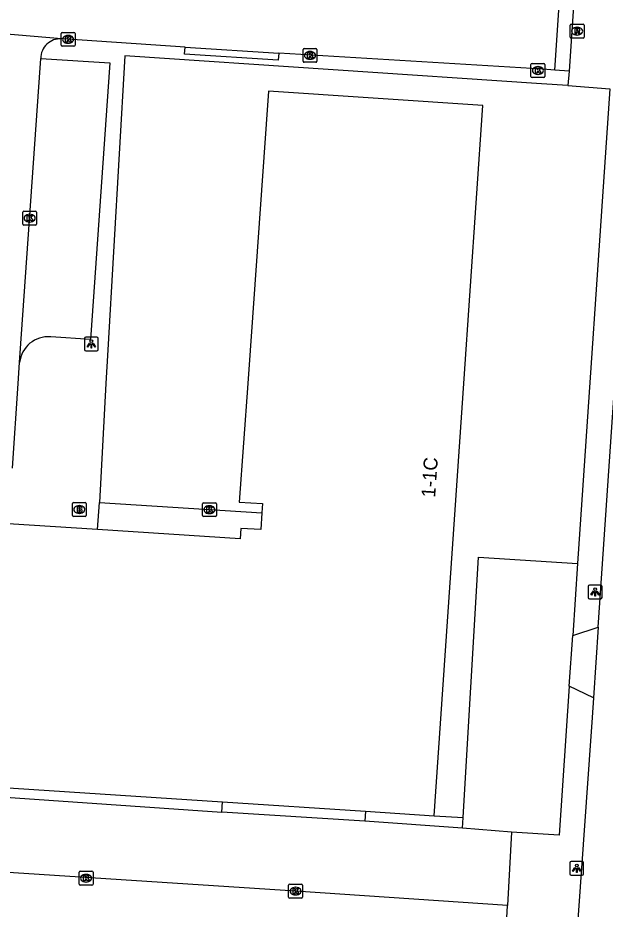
# Model space of a CAD drawing. Extents: x 161848 to 162726, y 385382 to 386521.
# Drawn here: x 161953.7 to 161996.1, y 385462 to 385526.4 of the extents above; entities that cross this region are included whole.
import ezdxf

# ---------------------------------------------------------------- set-up
doc = ezdxf.new("R2010")
doc.units = 0
for name, color, linetype in [('IMGEO_Brandkraan', 7, 'Continuous'), ('IMGEO_Fietspad_gesloten', 7, 'Continuous'), ('IMGEO_Kolk', 7, 'Continuous'), ('IMGEO_Lichtpunt', 7, 'Continuous'), ('IMGEO_Pand', 7, 'Continuous'), ('IMGEO_Pand_nummerreeks', 7, 'Continuous'), ('IMGEO_Parkeervlak_open', 7, 'Continuous'), ('IMGEO_Rijbaan_lokaal_open', 7, 'Continuous'), ('IMGEO_Rioolput', 7, 'Continuous'), ('IMGEO_Voetpad_open', 7, 'Continuous')]:
    doc.layers.add(name, color=color, linetype=linetype)

msp = doc.modelspace()

# ---------------------------------------------------------------- linework, layer by layer
at = {"layer": 'IMGEO_Brandkraan'}
for p, q in [((161957.602, 385490.47), (161957.602, 385491.322)), ((161957.677, 385491.396), (161958.529, 385491.396)), ((161958.603, 385491.322), (161958.603, 385490.47)), ((161958.09, 385491.176), (161958.115, 385491.176)), ((161958.529, 385490.396), (161957.677, 385490.396)), ((161958.113, 385490.616), (161958.088, 385490.616))]:
    msp.add_line(p, q, dxfattribs=at)
for points in [[(161957.602, 385490.47), (161957.602, 385491.322)], [(161957.677, 385491.396), (161958.529, 385491.396)], [(161958.603, 385491.322), (161958.603, 385490.47)], [(161957.95, 385491.096), (161957.95, 385490.696), (161958.163, 385490.696)], [(161958.181, 385491.096), (161957.95, 385491.096)], [(161958.129, 385491.015), (161958.075, 385491.015), (161958.075, 385490.939)], [(161958.075, 385490.939), (161958.128, 385490.939)], [(161958.137, 385490.863), (161958.075, 385490.863), (161958.075, 385490.782)], [(161958.075, 385490.782), (161958.137, 385490.782)], [(161958.529, 385490.396), (161957.677, 385490.396)]]:
    msp.add_lwpolyline(points, dxfattribs=at)
for centre, radius, start, end in [((161957.679, 385491.32), 0.0765, 91.55205, 178.44795), ((161957.679, 385491.32), 0.0765, 91.55205, 178.44795), ((161958.527, 385491.32), 0.0765, 1.55205, 88.44795), ((161958.527, 385491.32), 0.0765, 1.55205, 88.44795), ((161958.13, 385490.977), 0.0379, 267.82845, 90.93552), ((161958.138, 385490.822), 0.0404, 269.87594, 90.50774), ((161958.169, 385490.947), 0.251, 268.66757, 293.53466), ((161958.185, 385490.951), 0.145, 59.4692, 91.53667), ((161958.21, 385490.998), 0.0922, 285.51372, 58.15012), ((161958.215, 385490.806), 0.105, 301.31148, 78.98903), ((161957.679, 385490.472), 0.0765, 181.55205, 268.44795), ((161957.679, 385490.472), 0.0765, 181.55205, 268.44795), ((161958.527, 385490.472), 0.0765, 271.55205, 358.44795), ((161958.527, 385490.472), 0.0765, 271.55205, 358.44795)]:
    msp.add_arc(centre, radius, start, end, dxfattribs=at)
for centre, major_axis, ratio, start_param, end_param in [((161958.089, 385490.896), (-0.387, 0.002), 0.722429, 4.712389, 7.853982), ((161958.114, 385490.896), (-0.39, 0.002), 0.717154, 1.570796, 4.712389)]:
    msp.add_ellipse(centre, major_axis=major_axis, ratio=ratio, start_param=start_param, end_param=end_param, dxfattribs=at)
at = {"layer": 'IMGEO_Fietspad_gesloten'}
for points in [[(161995.573, 385482.388), (161998.276, 385522.203), (161998.624, 385527.317), (162001.78, 385573.813), (162002.14, 385579.104), (162003.371, 385597.237)], [(161995.573, 385482.388), (161995.227, 385477.289)], [(161995.227, 385477.289), (161995.132, 385475.887), (161992.735, 385441.913), (161992.311, 385435.632)]]:
    msp.add_lwpolyline(points, dxfattribs=at)
at = {"layer": 'IMGEO_Kolk'}
for p, q in [((161956.793, 385524.419), (161956.793, 385525.271)), ((161956.868, 385525.345), (161957.72, 385525.345)), ((161957.281, 385525.125), (161957.306, 385525.125)), ((161957.794, 385525.271), (161957.794, 385524.419)), ((161957.72, 385524.345), (161956.868, 385524.345)), ((161957.304, 385524.565), (161957.279, 385524.565)), ((161974.336, 385524.188), (161975.188, 385524.188)), ((161974.261, 385523.262), (161974.261, 385524.114)), ((161974.749, 385523.968), (161974.774, 385523.968)), ((161975.262, 385524.114), (161975.262, 385523.262)), ((161975.188, 385523.188), (161974.336, 385523.188)), ((161974.772, 385523.408), (161974.747, 385523.408)), ((161990.716, 385522.172), (161990.716, 385523.024)), ((161990.791, 385523.098), (161991.643, 385523.098)), ((161991.204, 385522.878), (161991.229, 385522.878)), ((161991.717, 385523.024), (161991.717, 385522.172)), ((161991.227, 385522.318), (161991.202, 385522.318)), ((161991.643, 385522.098), (161990.791, 385522.098)), ((161954.019, 385511.506), (161954.019, 385512.358)), ((161954.094, 385512.432), (161954.946, 385512.432)), ((161954.507, 385512.212), (161954.532, 385512.212)), ((161955.02, 385512.358), (161955.02, 385511.506)), ((161954.946, 385511.432), (161954.094, 385511.432)), ((161954.53, 385511.652), (161954.505, 385511.652)), ((161967.002, 385490.458), (161967.002, 385491.31)), ((161967.077, 385491.384), (161967.929, 385491.384)), ((161968.003, 385491.31), (161968.003, 385490.458)), ((161967.49, 385491.164), (161967.515, 385491.164)), ((161967.929, 385490.384), (161967.077, 385490.384)), ((161967.513, 385490.604), (161967.488, 385490.604)), ((161958.093, 385463.845), (161958.093, 385464.697)), ((161958.168, 385464.771), (161959.02, 385464.771)), ((161958.581, 385464.551), (161958.606, 385464.551)), ((161959.094, 385464.697), (161959.094, 385463.845)), ((161959.02, 385463.771), (161958.168, 385463.771)), ((161958.604, 385463.991), (161958.579, 385463.991)), ((161973.219, 385462.914), (161973.219, 385463.766)), ((161973.294, 385463.84), (161974.146, 385463.84)), ((161974.22, 385463.766), (161974.22, 385462.914)), ((161973.73, 385463.06), (161973.705, 385463.06)), ((161973.707, 385463.62), (161973.732, 385463.62)), ((161974.146, 385462.84), (161973.294, 385462.84))]:
    msp.add_line(p, q, dxfattribs=at)
for points in [[(161956.793, 385524.419), (161956.793, 385525.271)], [(161956.868, 385525.345), (161957.72, 385525.345)], [(161957.114, 385525.045), (161957.237, 385525.045), (161957.237, 385524.894), (161957.367, 385525.045), (161957.531, 385525.045), (161957.385, 385524.894), (161957.538, 385524.645), (161957.386, 385524.645), (161957.301, 385524.809), (161957.237, 385524.742), (161957.237, 385524.645), (161957.114, 385524.645), (161957.114, 385525.045)], [(161957.794, 385525.271), (161957.794, 385524.419)], [(161957.72, 385524.345), (161956.868, 385524.345)], [(161974.336, 385524.188), (161975.188, 385524.188)], [(161974.261, 385523.262), (161974.261, 385524.114)], [(161974.582, 385523.888), (161974.705, 385523.888), (161974.705, 385523.737), (161974.835, 385523.888), (161974.999, 385523.888), (161974.853, 385523.737), (161975.006, 385523.488), (161974.854, 385523.488), (161974.769, 385523.652), (161974.705, 385523.585), (161974.705, 385523.488), (161974.582, 385523.488), (161974.582, 385523.888)], [(161975.262, 385524.114), (161975.262, 385523.262)], [(161975.188, 385523.188), (161974.336, 385523.188)], [(161990.716, 385522.172), (161990.716, 385523.024)], [(161990.791, 385523.098), (161991.643, 385523.098)], [(161991.717, 385523.024), (161991.717, 385522.172)], [(161991.037, 385522.798), (161991.16, 385522.798), (161991.16, 385522.647), (161991.29, 385522.798), (161991.454, 385522.798), (161991.308, 385522.647), (161991.461, 385522.398), (161991.309, 385522.398), (161991.224, 385522.562), (161991.16, 385522.495), (161991.16, 385522.398), (161991.037, 385522.398), (161991.037, 385522.798)], [(161991.643, 385522.098), (161990.791, 385522.098)], [(161954.019, 385511.506), (161954.019, 385512.358)], [(161954.094, 385512.432), (161954.946, 385512.432)], [(161954.34, 385512.132), (161954.463, 385512.132), (161954.463, 385511.981), (161954.593, 385512.132), (161954.757, 385512.132), (161954.611, 385511.981), (161954.764, 385511.732), (161954.612, 385511.732), (161954.527, 385511.896), (161954.463, 385511.829), (161954.463, 385511.732), (161954.34, 385511.732), (161954.34, 385512.132)], [(161955.02, 385512.358), (161955.02, 385511.506)], [(161954.946, 385511.432), (161954.094, 385511.432)], [(161967.002, 385490.458), (161967.002, 385491.31)], [(161967.077, 385491.384), (161967.929, 385491.384)], [(161968.003, 385491.31), (161968.003, 385490.458)], [(161967.323, 385491.084), (161967.446, 385491.084), (161967.446, 385490.933), (161967.576, 385491.084), (161967.74, 385491.084), (161967.594, 385490.933), (161967.747, 385490.684), (161967.595, 385490.684), (161967.51, 385490.848), (161967.446, 385490.781), (161967.446, 385490.684), (161967.323, 385490.684), (161967.323, 385491.084)], [(161967.929, 385490.384), (161967.077, 385490.384)], [(161958.093, 385463.845), (161958.093, 385464.697)], [(161958.168, 385464.771), (161959.02, 385464.771)], [(161958.414, 385464.471), (161958.537, 385464.471), (161958.537, 385464.32), (161958.667, 385464.471), (161958.831, 385464.471), (161958.685, 385464.32), (161958.838, 385464.071), (161958.686, 385464.071), (161958.601, 385464.235), (161958.537, 385464.168), (161958.537, 385464.071), (161958.414, 385464.071), (161958.414, 385464.471)], [(161959.094, 385464.697), (161959.094, 385463.845)], [(161959.02, 385463.771), (161958.168, 385463.771)], [(161973.219, 385462.914), (161973.219, 385463.766)], [(161973.294, 385463.84), (161974.146, 385463.84)], [(161974.22, 385463.766), (161974.22, 385462.914)], [(161973.54, 385463.54), (161973.663, 385463.54), (161973.663, 385463.389), (161973.793, 385463.54), (161973.957, 385463.54), (161973.811, 385463.389), (161973.964, 385463.14), (161973.812, 385463.14), (161973.727, 385463.304), (161973.663, 385463.237), (161973.663, 385463.14), (161973.54, 385463.14), (161973.54, 385463.54)], [(161974.146, 385462.84), (161973.294, 385462.84)]]:
    msp.add_lwpolyline(points, dxfattribs=at)
for centre, start, end in [((161956.87, 385525.269), 91.55205, 178.44795), ((161956.87, 385525.269), 91.55205, 178.44795), ((161957.718, 385525.269), 1.55205, 88.44795), ((161957.718, 385525.269), 1.55205, 88.44795), ((161956.87, 385524.421), 181.55205, 268.44795), ((161956.87, 385524.421), 181.55205, 268.44795), ((161957.718, 385524.421), 271.55205, 358.44795), ((161957.718, 385524.421), 271.55205, 358.44795), ((161974.338, 385524.112), 91.55205, 178.44795), ((161974.338, 385524.112), 91.55205, 178.44795), ((161975.186, 385524.112), 1.55205, 88.44795), ((161975.186, 385524.112), 1.55205, 88.44795), ((161974.338, 385523.264), 181.55205, 268.44795), ((161974.338, 385523.264), 181.55205, 268.44795), ((161975.186, 385523.264), 271.55205, 358.44795), ((161975.186, 385523.264), 271.55205, 358.44795), ((161990.793, 385523.022), 91.55205, 178.44795), ((161990.793, 385523.022), 91.55205, 178.44795), ((161991.641, 385523.022), 1.55205, 88.44795), ((161991.641, 385523.022), 1.55205, 88.44795), ((161990.793, 385522.174), 181.55205, 268.44795), ((161990.793, 385522.174), 181.55205, 268.44795), ((161991.641, 385522.174), 271.55205, 358.44795), ((161991.641, 385522.174), 271.55205, 358.44795), ((161954.096, 385512.356), 91.55205, 178.44795), ((161954.096, 385512.356), 91.55205, 178.44795), ((161954.944, 385512.356), 1.55205, 88.44795), ((161954.944, 385512.356), 1.55205, 88.44795), ((161954.096, 385511.508), 181.55205, 268.44795), ((161954.096, 385511.508), 181.55205, 268.44795), ((161954.944, 385511.508), 271.55205, 358.44795), ((161954.944, 385511.508), 271.55205, 358.44795), ((161967.079, 385491.308), 91.55205, 178.44795), ((161967.079, 385491.308), 91.55205, 178.44795), ((161967.927, 385491.308), 1.55205, 88.44795), ((161967.927, 385491.308), 1.55205, 88.44795), ((161967.079, 385490.46), 181.55205, 268.44795), ((161967.079, 385490.46), 181.55205, 268.44795), ((161967.927, 385490.46), 271.55205, 358.44795), ((161967.927, 385490.46), 271.55205, 358.44795), ((161958.17, 385464.695), 91.55205, 178.44795), ((161958.17, 385464.695), 91.55205, 178.44795), ((161959.018, 385464.695), 1.55205, 88.44795), ((161959.018, 385464.695), 1.55205, 88.44795), ((161958.17, 385463.847), 181.55205, 268.44795), ((161958.17, 385463.847), 181.55205, 268.44795), ((161959.018, 385463.847), 271.55205, 358.44795), ((161959.018, 385463.847), 271.55205, 358.44795), ((161973.296, 385463.764), 91.55205, 178.44795), ((161973.296, 385463.764), 91.55205, 178.44795), ((161974.144, 385463.764), 1.55205, 88.44795), ((161974.144, 385463.764), 1.55205, 88.44795), ((161973.296, 385462.916), 181.55205, 268.44795), ((161973.296, 385462.916), 181.55205, 268.44795), ((161974.144, 385462.916), 271.55205, 358.44795), ((161974.144, 385462.916), 271.55205, 358.44795)]:
    msp.add_arc(centre, 0.0765, start, end, dxfattribs=at)
for centre, major_axis, ratio, start_param, end_param in [((161957.28, 385524.845), (-0.387, 0.002), 0.722429, 4.712389, 7.853982), ((161957.305, 385524.845), (-0.39, 0.002), 0.717154, 1.570796, 4.712389), ((161974.748, 385523.688), (-0.387, 0.002), 0.722429, 4.712389, 7.853982), ((161974.773, 385523.688), (-0.39, 0.002), 0.717154, 1.570796, 4.712389), ((161991.203, 385522.598), (-0.387, 0.002), 0.722429, 4.712389, 7.853982), ((161991.228, 385522.598), (-0.39, 0.002), 0.717154, 1.570796, 4.712389), ((161954.506, 385511.932), (-0.387, 0.002), 0.722429, 4.712389, 7.853982), ((161954.531, 385511.932), (-0.39, 0.002), 0.717154, 1.570796, 4.712389), ((161967.489, 385490.884), (-0.387, 0.002), 0.722429, 4.712389, 7.853982), ((161967.514, 385490.884), (-0.39, 0.002), 0.717154, 1.570796, 4.712389), ((161958.58, 385464.271), (-0.387, 0.002), 0.722429, 4.712389, 7.853982), ((161958.605, 385464.271), (-0.39, 0.002), 0.717154, 1.570796, 4.712389), ((161973.706, 385463.34), (-0.387, 0.002), 0.722429, 4.712389, 7.853982), ((161973.731, 385463.34), (-0.39, 0.002), 0.717154, 1.570796, 4.712389)]:
    msp.add_ellipse(centre, major_axis=major_axis, ratio=ratio, start_param=start_param, end_param=end_param, dxfattribs=at)
at = {"layer": 'IMGEO_Lichtpunt'}
for p, q in [((161958.473, 385503.248), (161958.473, 385502.441)), ((161958.473, 385503.248), (161958.473, 385502.441)), ((161959.375, 385503.343), (161958.567, 385503.343)), ((161959.375, 385503.343), (161958.567, 385503.343)), ((161959.469, 385502.441), (161959.469, 385503.248)), ((161959.469, 385502.441), (161959.469, 385503.248)), ((161958.567, 385502.347), (161959.375, 385502.347)), ((161958.567, 385502.347), (161959.375, 385502.347)), ((161994.849, 385485.348), (161994.849, 385484.541)), ((161994.849, 385485.348), (161994.849, 385484.541)), ((161995.751, 385485.443), (161994.943, 385485.443)), ((161995.751, 385485.443), (161994.943, 385485.443)), ((161995.845, 385484.541), (161995.845, 385485.348)), ((161995.845, 385484.541), (161995.845, 385485.348)), ((161994.943, 385484.447), (161995.751, 385484.447)), ((161994.943, 385484.447), (161995.751, 385484.447)), ((161993.519, 385465.391), (161993.519, 385464.584)), ((161993.519, 385465.391), (161993.519, 385464.584)), ((161994.421, 385465.486), (161993.613, 385465.486)), ((161994.421, 385465.486), (161993.613, 385465.486)), ((161994.515, 385464.584), (161994.515, 385465.391)), ((161994.515, 385464.584), (161994.515, 385465.391)), ((161993.613, 385464.49), (161994.421, 385464.49)), ((161993.613, 385464.49), (161994.421, 385464.49))]:
    msp.add_line(p, q, dxfattribs=at)
for points in [[(161958.847, 385502.912), (161958.886, 385502.884), (161958.698, 385502.622), (161958.66, 385502.649), (161958.847, 385502.912)], [(161959.059, 385502.884), (161959.097, 385502.911), (161959.284, 385502.649), (161959.245, 385502.621), (161959.059, 385502.884)], [(161958.949, 385502.864), (161958.996, 385502.864), (161958.996, 385502.542), (161958.949, 385502.542), (161958.949, 385502.864)], [(161995.223, 385485.012), (161995.262, 385484.984), (161995.074, 385484.722), (161995.036, 385484.749), (161995.223, 385485.012)], [(161995.325, 385484.964), (161995.372, 385484.964), (161995.372, 385484.642), (161995.325, 385484.642), (161995.325, 385484.964)], [(161995.435, 385484.984), (161995.473, 385485.011), (161995.66, 385484.749), (161995.621, 385484.721), (161995.435, 385484.984)], [(161993.893, 385465.055), (161993.932, 385465.027), (161993.744, 385464.765), (161993.706, 385464.792), (161993.893, 385465.055)], [(161993.995, 385465.007), (161994.042, 385465.007), (161994.042, 385464.685), (161993.995, 385464.685), (161993.995, 385465.007)], [(161994.105, 385465.027), (161994.143, 385465.054), (161994.33, 385464.792), (161994.291, 385464.764), (161994.105, 385465.027)]]:
    msp.add_lwpolyline(points, dxfattribs=at)
for centre in [(161958.972, 385503.046), (161995.348, 385485.146), (161994.018, 385465.189)]:
    msp.add_circle(centre, 0.0994, dxfattribs=at)
for centre, start, end in [((161958.567, 385503.248), 90, 180), ((161958.567, 385503.248), 90, 180), ((161959.375, 385503.248), 0, 90), ((161959.375, 385503.248), 0, 90), ((161958.567, 385502.441), 180, 270), ((161958.567, 385502.441), 180, 270), ((161959.375, 385502.441), 270, 0), ((161959.375, 385502.441), 270, 360), ((161994.943, 385485.348), 90, 180), ((161994.943, 385485.348), 90, 180), ((161995.751, 385485.348), 0, 90), ((161995.751, 385485.348), 0, 90), ((161994.943, 385484.541), 180, 270), ((161994.943, 385484.541), 180, 270), ((161995.751, 385484.541), 270, 0), ((161995.751, 385484.541), 270, 360), ((161993.613, 385465.391), 90, 180), ((161993.613, 385465.391), 90, 180), ((161994.421, 385465.391), 0, 90), ((161994.421, 385465.391), 0, 90), ((161993.613, 385464.584), 180, 270), ((161993.613, 385464.584), 180, 270), ((161994.421, 385464.584), 270, 0), ((161994.421, 385464.584), 270, 360)]:
    msp.add_arc(centre, 0.0946, start, end, dxfattribs=at)
at = {"layer": 'IMGEO_Pand'}
for points in [[(161983.733, 385468.78), (161985.862, 385500), (161987.231, 385520.078), (161971.769, 385521.102), (161970.267, 385500), (161969.657, 385491.425), (161971.324, 385491.319), (161971.281, 385490.646)], [(161959.412, 385489.446), (161932.077, 385491.193), (161930.866, 385472.24), (161968.434, 385469.781)], [(161971.281, 385490.646), (161971.205, 385489.442), (161969.757, 385489.533), (161969.709, 385488.788), (161959.412, 385489.446)], [(161968.434, 385469.781), (161978.768, 385469.105)], [(161978.768, 385469.105), (161983.733, 385468.78)]]:
    msp.add_lwpolyline(points, dxfattribs=at)
at = {"layer": 'IMGEO_Parkeervlak_open'}
for points in [[(161985.826, 385468.657), (161986.931, 385487.464), (161994.084, 385486.988)], [(161989.304, 385467.593), (161985.781, 385467.89)]]:
    msp.add_lwpolyline(points, dxfattribs=at)
at = {"layer": 'IMGEO_Rijbaan_lokaal_open'}
for points in [[(161992.427, 385522.615), (161992.777, 385527.666)], [(161993.81, 385527.611), (161993.463, 385522.542)], [(161956.819, 385524.879), (161949.175, 385525.537)], [(161965.744, 385524.286), (161956.884, 385524.873), (161956.819, 385524.879)], [(161965.744, 385524.286), (161972.505, 385523.839)], [(161992.427, 385522.615), (161991.565, 385522.692), (161972.505, 385523.839)], [(161953.795, 385501.507), (161955.322, 385523.473)], [(161993.463, 385522.542), (161992.427, 385522.615)], [(161953.29, 385493.878), (161953.69, 385500), (161953.795, 385501.507)], [(161989.02, 385462.302), (161973.719, 385463.339), (161924.082, 385466.568), (161926.246, 385500), (161926.302, 385500.859)], [(161988.372, 385450.247), (161989.02, 385462.302)]]:
    msp.add_lwpolyline(points, dxfattribs=at)
msp.add_arc((161956.724, 385523.48), 1.402, 86.11634, 180.29274, dxfattribs=at)
at = {"layer": 'IMGEO_Rioolput'}
for p, q in [((161993.546, 385525.011), (161993.546, 385525.863)), ((161993.621, 385525.937), (161994.473, 385525.937)), ((161994.034, 385525.717), (161994.059, 385525.717)), ((161994.547, 385525.863), (161994.547, 385525.011)), ((161994.473, 385524.937), (161993.621, 385524.937)), ((161994.057, 385525.157), (161994.032, 385525.157))]:
    msp.add_line(p, q, dxfattribs=at)
for points in [[(161993.546, 385525.011), (161993.546, 385525.863)], [(161993.621, 385525.937), (161994.473, 385525.937)], [(161994.135, 385525.635), (161993.883, 385525.637), (161993.883, 385525.237)], [(161994.061, 385525.556), (161994.007, 385525.556), (161994.007, 385525.475)], [(161994.007, 385525.475), (161994.059, 385525.475)], [(161994.547, 385525.863), (161994.547, 385525.011)], [(161994.473, 385524.937), (161993.621, 385524.937)], [(161993.883, 385525.237), (161994.007, 385525.237), (161994.007, 385525.399), (161994.018, 385525.399)], [(161994.065, 385525.37), (161994.136, 385525.237), (161994.276, 385525.237), (161994.211, 385525.363)]]:
    msp.add_lwpolyline(points, dxfattribs=at)
for centre, radius, start, end in [((161993.623, 385525.861), 0.0765, 91.55205, 178.44795), ((161993.623, 385525.861), 0.0765, 91.55205, 178.44795), ((161994.043, 385525.664), 0.19, 274.7715, 282.96867), ((161994.067, 385525.46), 0.0964, 77.00612, 93.18647), ((161994.081, 385525.517), 0.0378, 276.66336, 79.67722), ((161994.134, 385525.525), 0.109, 350.36119, 89.41601), ((161994.132, 385525.525), 0.112, 277.58423, 350.98172), ((161994.471, 385525.861), 0.0765, 1.55205, 88.44795), ((161994.471, 385525.861), 0.0765, 1.55205, 88.44795), ((161993.623, 385525.013), 0.0765, 181.55205, 268.44795), ((161993.623, 385525.013), 0.0765, 181.55205, 268.44795), ((161994.017, 385525.346), 0.0533, 26.02933, 88.69889), ((161994.116, 385525.31), 0.108, 29.51342, 73.79051), ((161994.471, 385525.013), 0.0765, 271.55205, 358.44795), ((161994.471, 385525.013), 0.0765, 271.55205, 358.44795)]:
    msp.add_arc(centre, radius, start, end, dxfattribs=at)
for centre, major_axis, ratio, start_param, end_param in [((161994.033, 385525.437), (-0.387, 0.002), 0.722429, 4.712389, 7.853982), ((161994.058, 385525.437), (-0.39, 0.002), 0.717154, 1.570796, 4.712389)]:
    msp.add_ellipse(centre, major_axis=major_axis, ratio=ratio, start_param=start_param, end_param=end_param, dxfattribs=at)
at = {"layer": 'IMGEO_Voetpad_open'}
for points in [[(161972.505, 385523.839), (161972.472, 385523.341), (161965.711, 385523.788), (161965.744, 385524.286)], [(161993.387, 385521.503), (161991.476, 385521.643), (161961.383, 385523.654), (161960.165, 385502.421), (161960.031, 385500), (161959.557, 385491.4)], [(161955.322, 385523.473), (161960.311, 385523.142), (161958.923, 385503.177), (161956.04, 385503.368)], [(161993.463, 385522.542), (161993.387, 385521.503)], [(161993.387, 385521.503), (161996.406, 385521.282), (161994.084, 385486.988)], [(161926.302, 385500.859), (161932.035, 385500.475), (161932.013, 385500), (161931.448, 385491.214), (161930.191, 385471.68), (161968.387, 385469.051)], [(161959.412, 385489.446), (161959.557, 385491.4)], [(161959.557, 385491.4), (161971.281, 385490.646)], [(161994.084, 385486.988), (161993.732, 385481.801)], [(161993.732, 385481.801), (161995.573, 385482.388)], [(161993.484, 385478.14), (161993.732, 385481.801)], [(161993.484, 385478.14), (161992.755, 385467.369), (161989.304, 385467.593)], [(161995.227, 385477.289), (161993.484, 385478.14)], [(161968.387, 385469.051), (161968.434, 385469.781)], [(161978.722, 385468.391), (161968.387, 385469.051)], [(161978.768, 385469.105), (161978.722, 385468.391)], [(161983.733, 385468.78), (161985.826, 385468.657)], [(161985.781, 385467.89), (161978.722, 385468.391)], [(161985.781, 385467.89), (161985.826, 385468.657)], [(161989.304, 385467.593), (161989.02, 385462.302)]]:
    msp.add_lwpolyline(points, dxfattribs=at)
msp.add_arc((161955.864, 385501.295), 2.08, 85.15062, 174.16367, dxfattribs=at)

# ---------------------------------------------------------------- texts
at = {"layer": 'IMGEO_Pand_nummerreeks'}
msp.add_text('1-1C', height=1, rotation=86.09837, dxfattribs=at).set_placement((161983.795, 385491.744))

doc.saveas('drawing.dxf')
